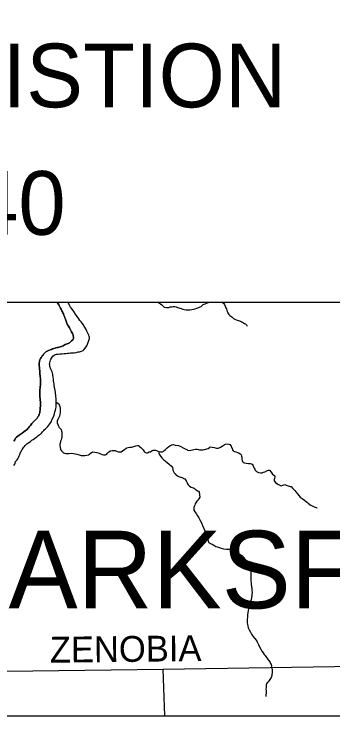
# Model space of a CAD drawing. Extents: x 0 to 34, y 0 to 22.
# Drawn here: x 5.074 to 5.775, y 14.1 to 15.642 of the extents above; entities that cross this region are included whole.
import ezdxf

# ---------------------------------------------------------------- set-up
doc = ezdxf.new("R2010")
doc.units = 0
for name, color, linetype in [('GM_X_Corporation', 7, 'Continuous'), ('GM_X_County_Road', 7, 'Continuous'), ('GM_X_County_Road_Text', 7, 'Continuous'), ('GM_X_Major_River', 7, 'Continuous'), ('GM_X_Minor_River', 7, 'Continuous'), ('GM_X_Township_Road', 7, 'Continuous'), ('GM_X_Township_Text', 7, 'Continuous'), ('SH_Text', 7, 'Continuous')]:
    doc.layers.add(name, color=color, linetype=linetype)

msp = doc.modelspace()

# ---------------------------------------------------------------- linework, layer by layer
at = {"layer": 'GM_X_Corporation'}
msp.add_lwpolyline([(2.1, 20.2456), (2.1, 14.1), (8.0383, 14.1), (8.035, 14.2498), (8.0349, 14.2572), (8.0297, 14.4963), (8.0262, 14.6555), (8.0153, 15.2273), (7.992, 16.4534)], dxfattribs=at)
msp.add_lwpolyline([(3.6901, 15.2048), (3.5209, 15.2041), (2.7366, 15.2014), (2.7422, 14.8151), (2.7753, 14.1537), (2.7761, 14.1), (8.0383, 14.1), (8.035, 14.2498), (8.0349, 14.2572), (8.0297, 14.4963), (8.0262, 14.6555), (8.0153, 15.2273), (6.9496, 15.2134), (6.7394, 15.212), (6.1026, 15.2145), (5.9099, 15.2138), (5.9099, 15.0085), (3.6901, 15.0085)], close=True, dxfattribs=at)
at = {"layer": 'GM_X_County_Road'}
msp.add_lwpolyline([(4.3719, 14.1278), (4.3787, 14.1315), (4.3915, 14.1348), (4.4565, 14.1401), (4.5144, 14.1437), (4.5421, 14.1432), (4.5592, 14.1407), (4.571, 14.1369), (4.5894, 14.1297), (4.6067, 14.1224), (4.6223, 14.1196), (4.6839, 14.1382), (4.8054, 14.1766), (4.8436, 14.1889), (4.8607, 14.1933), (4.8848, 14.1961), (5.4016, 14.2029), (5.8255, 14.2097), (6.2339, 14.2154), (6.3212, 14.2172), (6.4144, 14.2189), (6.6754, 14.2251), (6.9836, 14.2295)], dxfattribs=at)
at = {"layer": 'GM_X_Major_River'}
for points in [[(5.1692, 15.0085), (5.1698, 15.0073), (5.1721, 15.0035), (5.1743, 14.9989), (5.1758, 14.9962), (5.1773, 14.9939), (5.178, 14.992), (5.1791, 14.9901), (5.1802, 14.9878), (5.1814, 14.9859), (5.1825, 14.9832), (5.1836, 14.9805), (5.1847, 14.9778), (5.1858, 14.9748), (5.1873, 14.9717), (5.1887, 14.9671), (5.1898, 14.9633), (5.1917, 14.9595), (5.1935, 14.9561), (5.1958, 14.9526), (5.1976, 14.9496), (5.1991, 14.9469), (5.2006, 14.9442), (5.2025, 14.9404), (5.2036, 14.9373), (5.2039, 14.9354), (5.2047, 14.9324), (5.205, 14.9289), (5.2031, 14.9263), (5.2004, 14.9244)], [(5.2004, 14.9244), (5.2031, 14.9263), (5.205, 14.9289), (5.2047, 14.9324), (5.2039, 14.9354), (5.2036, 14.9373), (5.2025, 14.9404), (5.2006, 14.9442), (5.1991, 14.9469), (5.1976, 14.9496), (5.1958, 14.9526), (5.1935, 14.9561), (5.1917, 14.9595), (5.1898, 14.9633), (5.1887, 14.9671), (5.1873, 14.9717), (5.1858, 14.9748), (5.1847, 14.9778), (5.1836, 14.9805), (5.1825, 14.9832), (5.1814, 14.9859), (5.1802, 14.9878), (5.1791, 14.9901), (5.178, 14.992), (5.1773, 14.9939), (5.1758, 14.9962), (5.1743, 14.9989), (5.1721, 15.0035), (5.1698, 15.0073), (5.1692, 15.0085)], [(5.2322, 14.9111), (5.2345, 14.9149), (5.236, 14.9191), (5.238, 14.9229), (5.2392, 14.927), (5.24, 14.9293), (5.2396, 14.9312), (5.2393, 14.9339), (5.2385, 14.9369), (5.2341, 14.9457), (5.2322, 14.9491), (5.23, 14.9526), (5.2281, 14.9557), (5.2263, 14.9595), (5.2236, 14.9626), (5.2214, 14.9656), (5.2188, 14.9687), (5.2162, 14.9725), (5.2128, 14.9775), (5.2091, 14.9829), (5.2053, 14.9886), (5.2016, 14.9936), (5.1982, 14.9982), (5.1956, 15.0028), (5.193, 15.0074), (5.1925, 15.0085)], [(5.2322, 14.9111), (5.2345, 14.9149), (5.236, 14.9191), (5.238, 14.9229), (5.2392, 14.927), (5.24, 14.9293), (5.2396, 14.9312), (5.2393, 14.9339), (5.2385, 14.9369), (5.2341, 14.9457), (5.2322, 14.9491), (5.23, 14.9526), (5.2281, 14.9557), (5.2263, 14.9595), (5.2236, 14.9626), (5.2214, 14.9656), (5.2188, 14.9687), (5.2162, 14.9725), (5.2128, 14.9775), (5.2091, 14.9829), (5.2053, 14.9886), (5.2016, 14.9936), (5.1982, 14.9982), (5.1956, 15.0028), (5.193, 15.0074), (5.1925, 15.0085)], [(5.2004, 14.9244), (5.1981, 14.9218), (5.1961, 14.9199), (5.1927, 14.9181), (5.1904, 14.9173), (5.1866, 14.9159), (5.1839, 14.9144), (5.1816, 14.9133), (5.1786, 14.9118), (5.1755, 14.9107), (5.1732, 14.9103), (5.1713, 14.9096), (5.1686, 14.9092), (5.166, 14.9085), (5.1641, 14.9078), (5.1614, 14.907), (5.1587, 14.9063), (5.1561, 14.9052), (5.153, 14.9041), (5.1499, 14.9026), (5.1469, 14.9011), (5.1442, 14.8996), (5.1415, 14.8974), (5.1388, 14.8948), (5.1377, 14.8929), (5.1361, 14.891), (5.135, 14.8891), (5.1334, 14.8872), (5.1322, 14.8853), (5.1307, 14.8823), (5.1299, 14.8797), (5.1299, 14.8774), (5.1295, 14.8755), (5.1294, 14.8736), (5.1294, 14.8713), (5.1294, 14.869), (5.1297, 14.866), (5.1297, 14.8637), (5.1301, 14.861), (5.1304, 14.8587), (5.1304, 14.8565), (5.1307, 14.8538), (5.1307, 14.8504), (5.1314, 14.8477), (5.1321, 14.839), (5.132, 14.8355), (5.132, 14.8325), (5.132, 14.8295), (5.1319, 14.8268), (5.1315, 14.8234), (5.1311, 14.8204), (5.131, 14.8173), (5.1306, 14.8131), (5.1306, 14.8093), (5.1309, 14.8052), (5.1309, 14.8014), (5.1312, 14.7975), (5.1315, 14.7937), (5.1319, 14.7903), (5.1322, 14.7873), (5.1322, 14.7839), (5.1321, 14.7804), (5.1317, 14.7766), (5.1313, 14.7721), (5.1308, 14.7687), (5.1304, 14.766), (5.1293, 14.763), (5.1281, 14.7596), (5.1265, 14.7569), (5.1246, 14.7543), (5.1223, 14.7517), (5.1196, 14.749), (5.1173, 14.7468), (5.115, 14.7445), (5.1127, 14.7423), (5.1099, 14.7381), (5.1069, 14.7351), (5.1057, 14.7332), (5.1042, 14.7314), (5.1026, 14.7295), (5.1007, 14.728), (5.0984, 14.7261), (5.0953, 14.7242), (5.0915, 14.7216), (5.0877, 14.7186), (5.085, 14.7168), (5.0823, 14.7149), (5.0796, 14.7126), (5.0773, 14.71), (5.0754, 14.7066), (5.0734, 14.7036)], [(5.0734, 14.7036), (5.0754, 14.7066), (5.0773, 14.71), (5.0796, 14.7126), (5.0823, 14.7149), (5.085, 14.7168), (5.0877, 14.7186), (5.0915, 14.7216), (5.0953, 14.7242), (5.0984, 14.7261), (5.1007, 14.728), (5.1026, 14.7295), (5.1042, 14.7314), (5.1057, 14.7332), (5.1069, 14.7351), (5.1099, 14.7381), (5.1127, 14.7423), (5.115, 14.7445), (5.1173, 14.7468), (5.1196, 14.749), (5.1223, 14.7517), (5.1246, 14.7543), (5.1265, 14.7569), (5.1281, 14.7596), (5.1293, 14.763), (5.1304, 14.766), (5.1308, 14.7687), (5.1313, 14.7721), (5.1317, 14.7766), (5.1321, 14.7804), (5.1322, 14.7839), (5.1322, 14.7873), (5.1319, 14.7903), (5.1315, 14.7937), (5.1312, 14.7975), (5.1309, 14.8014), (5.1309, 14.8052), (5.1306, 14.8093), (5.1306, 14.8131), (5.131, 14.8173), (5.1311, 14.8204), (5.1315, 14.8234), (5.1319, 14.8268), (5.132, 14.8295), (5.132, 14.8325), (5.132, 14.8355), (5.1321, 14.839), (5.1314, 14.8477), (5.1307, 14.8504), (5.1307, 14.8538), (5.1304, 14.8565), (5.1304, 14.8587), (5.1301, 14.861), (5.1297, 14.8637), (5.1297, 14.866), (5.1294, 14.869), (5.1294, 14.8713), (5.1294, 14.8736), (5.1295, 14.8755), (5.1299, 14.8774), (5.1299, 14.8797), (5.1307, 14.8823), (5.1322, 14.8853), (5.1334, 14.8872), (5.135, 14.8891), (5.1361, 14.891), (5.1377, 14.8929), (5.1388, 14.8948), (5.1415, 14.8974), (5.1442, 14.8996), (5.1469, 14.9011), (5.1499, 14.9026), (5.153, 14.9041), (5.1561, 14.9052), (5.1587, 14.9063), (5.1614, 14.907), (5.1641, 14.9078), (5.166, 14.9085), (5.1686, 14.9092), (5.1713, 14.9096), (5.1732, 14.9103), (5.1755, 14.9107), (5.1786, 14.9118), (5.1816, 14.9133), (5.1839, 14.9144), (5.1866, 14.9159), (5.1904, 14.9173), (5.1927, 14.9181), (5.1961, 14.9199), (5.1981, 14.9218), (5.2004, 14.9244)], [(5.0766, 14.6557), (5.0774, 14.6591), (5.0805, 14.6628), (5.0825, 14.6651), (5.084, 14.6681), (5.0852, 14.6711), (5.0864, 14.6742), (5.0875, 14.6772), (5.0887, 14.6795), (5.0903, 14.6821), (5.0914, 14.6844), (5.0926, 14.6863), (5.0949, 14.6897), (5.0965, 14.6915), (5.0984, 14.6942), (5.1019, 14.6979), (5.1065, 14.7005), (5.1099, 14.7032), (5.1134, 14.7062), (5.116, 14.7076), (5.1218, 14.7114), (5.1237, 14.7133), (5.1264, 14.7155), (5.1291, 14.7174), (5.1318, 14.7192), (5.1345, 14.7215), (5.1368, 14.7245), (5.1391, 14.7268), (5.141, 14.729), (5.1429, 14.7305), (5.146, 14.7335), (5.1483, 14.7362), (5.1506, 14.7388), (5.1529, 14.7418), (5.1557, 14.7459), (5.158, 14.752), (5.1607, 14.7573), (5.1619, 14.7611), (5.1631, 14.7645), (5.1639, 14.7679), (5.1651, 14.7721), (5.1659, 14.7755), (5.1663, 14.7781), (5.1663, 14.7815), (5.1664, 14.785), (5.1664, 14.7888), (5.1665, 14.7926), (5.1662, 14.7975), (5.1658, 14.8017), (5.1655, 14.8051), (5.1652, 14.8085), (5.1648, 14.8116), (5.1645, 14.815), (5.1638, 14.8188), (5.1627, 14.8226), (5.1623, 14.8261), (5.162, 14.8295), (5.1616, 14.8325), (5.1609, 14.836), (5.1606, 14.8382), (5.1606, 14.8409), (5.1602, 14.8432), (5.1599, 14.8451), (5.1595, 14.8478), (5.1592, 14.8504), (5.1585, 14.8531), (5.1574, 14.8562), (5.1563, 14.8592), (5.1548, 14.8619), (5.1529, 14.868), (5.1526, 14.8707), (5.1522, 14.8729), (5.1523, 14.876), (5.1531, 14.879), (5.1539, 14.8817), (5.155, 14.8839), (5.1566, 14.8862), (5.1581, 14.8884), (5.1593, 14.8903), (5.162, 14.8926), (5.165, 14.8944), (5.167, 14.8948), (5.1708, 14.8951), (5.1749, 14.8955), (5.1795, 14.8958), (5.1845, 14.8961), (5.1879, 14.8965), (5.1917, 14.8968), (5.1943, 14.8971), (5.1978, 14.8975), (5.202, 14.8978), (5.2061, 14.8981), (5.2107, 14.8988), (5.2149, 14.8996), (5.2179, 14.8999), (5.2202, 14.9006), (5.2225, 14.9014), (5.2256, 14.9032), (5.2275, 14.9047), (5.2294, 14.9074), (5.2322, 14.9111)], [(5.0766, 14.6557), (5.0774, 14.6591), (5.0805, 14.6628), (5.0825, 14.6651), (5.084, 14.6681), (5.0852, 14.6711), (5.0864, 14.6742), (5.0875, 14.6772), (5.0887, 14.6795), (5.0903, 14.6821), (5.0914, 14.6844), (5.0926, 14.6863), (5.0949, 14.6897), (5.0965, 14.6915), (5.0984, 14.6942), (5.1019, 14.6979), (5.1065, 14.7005), (5.1099, 14.7032), (5.1134, 14.7062), (5.116, 14.7076), (5.1218, 14.7114), (5.1237, 14.7133), (5.1264, 14.7155), (5.1291, 14.7174), (5.1318, 14.7192), (5.1345, 14.7215), (5.1368, 14.7245), (5.1391, 14.7268), (5.141, 14.729), (5.1429, 14.7305), (5.146, 14.7335), (5.1483, 14.7362), (5.1506, 14.7388), (5.1529, 14.7418), (5.1557, 14.7459), (5.158, 14.752), (5.1607, 14.7573), (5.1619, 14.7611), (5.1631, 14.7645), (5.1639, 14.7679), (5.1651, 14.7721), (5.1659, 14.7755), (5.1663, 14.7781), (5.1663, 14.7815), (5.1664, 14.785), (5.1664, 14.7888), (5.1665, 14.7926), (5.1662, 14.7975), (5.1658, 14.8017), (5.1655, 14.8051), (5.1652, 14.8085), (5.1648, 14.8116), (5.1645, 14.815), (5.1638, 14.8188), (5.1627, 14.8226), (5.1623, 14.8261), (5.162, 14.8295), (5.1616, 14.8325), (5.1609, 14.836), (5.1606, 14.8382), (5.1606, 14.8409), (5.1602, 14.8432), (5.1599, 14.8451), (5.1595, 14.8478), (5.1592, 14.8504), (5.1585, 14.8531), (5.1574, 14.8562), (5.1563, 14.8592), (5.1548, 14.8619), (5.1529, 14.868), (5.1526, 14.8707), (5.1522, 14.8729), (5.1523, 14.876), (5.1531, 14.879), (5.1539, 14.8817), (5.155, 14.8839), (5.1566, 14.8862), (5.1581, 14.8884), (5.1593, 14.8903), (5.162, 14.8926), (5.165, 14.8944), (5.167, 14.8948), (5.1708, 14.8951), (5.1749, 14.8955), (5.1795, 14.8958), (5.1845, 14.8961), (5.1879, 14.8965), (5.1917, 14.8968), (5.1943, 14.8971), (5.1978, 14.8975), (5.202, 14.8978), (5.2061, 14.8981), (5.2107, 14.8988), (5.2149, 14.8996), (5.2179, 14.8999), (5.2202, 14.9006), (5.2225, 14.9014), (5.2256, 14.9032), (5.2275, 14.9047), (5.2294, 14.9074), (5.2322, 14.9111)], [(5.0735, 14.65), (5.0755, 14.653), (5.0766, 14.6557)], [(5.0735, 14.65), (5.0755, 14.653), (5.0766, 14.6557)]]:
    msp.add_lwpolyline(points, dxfattribs=at)
at = {"layer": 'GM_X_Minor_River'}
for points in [[(5.3908, 15.0085), (5.3915, 15.0081), (5.3956, 15.0054), (5.399, 15.003), (5.402, 15), (5.4043, 14.9984), (5.4088, 14.9972), (5.4118, 14.9972), (5.4141, 14.9975), (5.4172, 14.9986), (5.4206, 14.999), (5.4237, 14.9993), (5.4271, 14.9993), (5.4305, 14.9985), (5.4335, 14.9977), (5.4362, 14.9969), (5.4388, 14.9957), (5.4411, 14.9949), (5.443, 14.9942), (5.4449, 14.9934), (5.4479, 14.993), (5.4521, 14.9925), (5.4559, 14.9921), (5.4601, 14.9924), (5.4646, 14.9931), (5.4688, 14.9938), (5.4723, 14.9946), (5.4761, 14.9957), (5.4799, 14.9975), (5.4833, 14.9986), (5.4852, 14.9994), (5.4899, 15.0039), (5.4941, 15.0053), (5.5017, 15.0085)], [(5.5325, 15.0085), (5.5332, 15.0079), (5.5351, 15.006), (5.5366, 15.0037), (5.5381, 15.0002), (5.5396, 14.9964), (5.5411, 14.9941), (5.5418, 14.9918), (5.5425, 14.9884)], [(5.5425, 14.9884), (5.544, 14.9854), (5.5459, 14.9823), (5.5485, 14.9796), (5.5526, 14.9765), (5.5568, 14.9734), (5.5605, 14.9711), (5.5643, 14.9695), (5.567, 14.9687), (5.57, 14.9679), (5.5719, 14.9672), (5.5742, 14.966), (5.5764, 14.9648), (5.5787, 14.9637), (5.5806, 14.9625), (5.5825, 14.9617), (5.5851, 14.959), (5.5864, 14.9566)], [(5.1664, 14.7892), (5.1721, 14.7857), (5.1732, 14.7834), (5.1743, 14.7799), (5.175, 14.7765), (5.1757, 14.7685), (5.1757, 14.7662), (5.1749, 14.7628), (5.1737, 14.7587), (5.1717, 14.7545), (5.1702, 14.7511), (5.169, 14.7488), (5.1686, 14.7466), (5.1689, 14.7439), (5.17, 14.7405), (5.1719, 14.737), (5.1734, 14.734), (5.1749, 14.732), (5.1775, 14.729), (5.1786, 14.7259), (5.1793, 14.7232), (5.1793, 14.7191), (5.1792, 14.716), (5.1788, 14.7134), (5.1784, 14.7099), (5.1772, 14.7065), (5.1764, 14.7039), (5.176, 14.7016), (5.1756, 14.6993), (5.1748, 14.6971), (5.1748, 14.6944), (5.1751, 14.6906), (5.1762, 14.6856), (5.1781, 14.6822), (5.1807, 14.6799), (5.183, 14.6783), (5.1852, 14.6776), (5.1875, 14.6768), (5.1906, 14.6764), (5.1947, 14.6767), (5.2001, 14.6774), (5.2046, 14.6769), (5.2084, 14.6761), (5.2118, 14.6753), (5.2171, 14.6734), (5.2213, 14.6722), (5.2255, 14.6721), (5.2297, 14.6721), (5.2342, 14.6728), (5.2377, 14.6735), (5.2396, 14.675), (5.2415, 14.6765), (5.2465, 14.6799), (5.2514, 14.6798), (5.256, 14.6786), (5.2609, 14.677), (5.2643, 14.6762), (5.2677, 14.6743), (5.2703, 14.6735), (5.2726, 14.6735), (5.2753, 14.6738), (5.2776, 14.6749), (5.2795, 14.6772), (5.2826, 14.6802), (5.286, 14.6821), (5.2898, 14.6832), (5.2933, 14.6835), (5.2963, 14.6831), (5.2993, 14.6815), (5.3027, 14.6803), (5.305, 14.6799), (5.3069, 14.6799), (5.3096, 14.6806), (5.3123, 14.6821), (5.315, 14.6844), (5.3169, 14.6855), (5.3203, 14.6881), (5.3222, 14.6889), (5.3245, 14.69), (5.3291, 14.6903), (5.3325, 14.6906), (5.3348, 14.691), (5.3375, 14.6921), (5.3417, 14.6936), (5.3455, 14.6943), (5.3474, 14.6943), (5.35, 14.6923), (5.353, 14.69), (5.3557, 14.6869), (5.3579, 14.6843), (5.3601, 14.6812), (5.3613, 14.6793), (5.3632, 14.6785), (5.3654, 14.6777), (5.3677, 14.6784)], [(5.3677, 14.6784), (5.3712, 14.6799), (5.3742, 14.6806), (5.3777, 14.6829), (5.3799, 14.6836), (5.3822, 14.684), (5.3849, 14.6836), (5.3872, 14.6831), (5.3898, 14.682), (5.3928, 14.6812), (5.3959, 14.6804), (5.3982, 14.6804), (5.4001, 14.6803), (5.402, 14.6811), (5.4043, 14.6833), (5.407, 14.6852), (5.4089, 14.6878), (5.4108, 14.6893), (5.4143, 14.6919), (5.4162, 14.6931), (5.4181, 14.6942), (5.42, 14.6953), (5.4219, 14.6957), (5.4246, 14.696), (5.4284, 14.6952), (5.4356, 14.694), (5.4409, 14.692), (5.4458, 14.6893), (5.4499, 14.687), (5.4537, 14.6854), (5.4556, 14.6842), (5.4586, 14.6834), (5.4624, 14.6838), (5.4662, 14.6849), (5.4693, 14.6856), (5.4727, 14.6863), (5.4746, 14.6863), (5.4765, 14.6859), (5.4792, 14.6851), (5.4815, 14.6847), (5.4845, 14.6847), (5.4887, 14.6846), (5.4929, 14.6853), (5.5009, 14.6875), (5.5036, 14.6901), (5.5055, 14.6912), (5.5093, 14.6908), (5.5142, 14.6896), (5.5191, 14.6884), (5.5226, 14.6884), (5.5252, 14.6887), (5.5275, 14.6906), (5.5313, 14.6925), (5.534, 14.6939), (5.5382, 14.6973), (5.5424, 14.6976), (5.5462, 14.6968), (5.5485, 14.6961), (5.5511, 14.6926), (5.5522, 14.6899), (5.5533, 14.6873), (5.5544, 14.6846), (5.5556, 14.6827), (5.559, 14.6807), (5.5616, 14.6799), (5.565, 14.6791), (5.5684, 14.678), (5.5711, 14.6756), (5.5733, 14.6737), (5.5744, 14.6707), (5.5748, 14.6688), (5.5747, 14.6665), (5.5751, 14.6638), (5.5758, 14.6615), (5.5766, 14.6592), (5.5781, 14.6569), (5.5807, 14.6558), (5.5841, 14.655), (5.5891, 14.6549), (5.591, 14.6549), (5.5929, 14.6549), (5.5974, 14.6533), (5.5996, 14.6495), (5.6007, 14.6472), (5.6022, 14.6445), (5.6033, 14.6422), (5.6041, 14.6403), (5.6067, 14.6372), (5.6097, 14.6357), (5.6116, 14.6349), (5.6158, 14.6344), (5.6196, 14.6344), (5.6227, 14.6355), (5.6253, 14.6366), (5.6272, 14.637), (5.6291, 14.6385), (5.6314, 14.6396), (5.6333, 14.6403), (5.6353, 14.6403), (5.639, 14.6353), (5.6424, 14.6311)], [(5.393, 14.6811), (5.3924, 14.6774), (5.3928, 14.6751), (5.3958, 14.6709), (5.3991, 14.6674), (5.4014, 14.6651), (5.4036, 14.6628), (5.4067, 14.6601), (5.4104, 14.6566), (5.4153, 14.6528), (5.4202, 14.6485), (5.4224, 14.6459), (5.4228, 14.6424), (5.4231, 14.6398), (5.4242, 14.6371), (5.4257, 14.6344), (5.428, 14.6317), (5.4306, 14.629), (5.4329, 14.6279), (5.4351, 14.6267), (5.4378, 14.6252), (5.4404, 14.6244), (5.445, 14.6228), (5.4476, 14.622), (5.4495, 14.6208), (5.451, 14.6185), (5.4532, 14.6151), (5.4543, 14.612), (5.4555, 14.6097), (5.457, 14.6074), (5.46, 14.6047), (5.4634, 14.6024), (5.4679, 14.6009), (5.4702, 14.6001), (5.4724, 14.5985), (5.4743, 14.5966), (5.4773, 14.5947), (5.4796, 14.5935), (5.4811, 14.5916), (5.4821, 14.5805), (5.4805, 14.5771), (5.4778, 14.5741), (5.4755, 14.5719), (5.4736, 14.5685), (5.4724, 14.5658), (5.4712, 14.5632), (5.4701, 14.5605), (5.4693, 14.5583), (5.4693, 14.5552), (5.4696, 14.5522), (5.4711, 14.5487), (5.4741, 14.5445), (5.4774, 14.5399), (5.4804, 14.535), (5.4834, 14.5296), (5.4864, 14.5239), (5.4886, 14.5185), (5.4912, 14.512), (5.4934, 14.5067), (5.4956, 14.5009), (5.4974, 14.4952), (5.4992, 14.4895), (5.5007, 14.4849), (5.5018, 14.4819), (5.5037, 14.4803), (5.506, 14.4788), (5.5094, 14.4772), (5.5135, 14.4749), (5.5177, 14.4722), (5.5237, 14.4706), (5.5294, 14.4686), (5.5347, 14.4674), (5.5408, 14.4666), (5.5461, 14.4661), (5.5507, 14.4653), (5.5552, 14.4645), (5.5597, 14.4626), (5.5635, 14.4606), (5.5669, 14.4579), (5.5707, 14.4552), (5.5752, 14.4514), (5.5782, 14.4483), (5.5812, 14.4444), (5.5842, 14.441), (5.5864, 14.4379), (5.5912, 14.4265), (5.5927, 14.4223), (5.5942, 14.4177), (5.5945, 14.4131), (5.5944, 14.4078), (5.5944, 14.404), (5.5947, 14.3998), (5.5947, 14.396), (5.595, 14.393), (5.595, 14.3903), (5.5953, 14.388), (5.5957, 14.3857), (5.5961, 14.3838), (5.5964, 14.3812), (5.5967, 14.3785), (5.5971, 14.3755)], [(5.6424, 14.6311), (5.645, 14.6292), (5.6473, 14.6276), (5.6472, 14.6257), (5.6464, 14.6219), (5.6456, 14.6196), (5.6456, 14.6166), (5.6486, 14.6131), (5.6539, 14.6093), (5.6595, 14.6062), (5.6614, 14.6054), (5.6649, 14.6069), (5.6672, 14.608), (5.6691, 14.6083), (5.6725, 14.6068), (5.6766, 14.6052), (5.6808, 14.6044), (5.6831, 14.604), (5.6868, 14.5998), (5.6891, 14.5975), (5.691, 14.5952), (5.6932, 14.5921), (5.697, 14.5879), (5.7, 14.5844), (5.7033, 14.581), (5.7075, 14.5775), (5.7124, 14.574), (5.7165, 14.5709), (5.7192, 14.5686), (5.721, 14.5671), (5.7244, 14.5644), (5.7267, 14.5628), (5.7297, 14.5613), (5.7335, 14.5597), (5.7361, 14.5589), (5.738, 14.5577), (5.7399, 14.5573), (5.7407, 14.5569)], [(5.5971, 14.3755), (5.5974, 14.3713), (5.597, 14.3679), (5.597, 14.3641), (5.5961, 14.3599), (5.5953, 14.3553), (5.5937, 14.3497), (5.5922, 14.3444), (5.5906, 14.3394), (5.5894, 14.3353), (5.5886, 14.3311), (5.5878, 14.3273), (5.5873, 14.322), (5.5869, 14.3171), (5.5865, 14.3129), (5.5864, 14.3095), (5.5867, 14.3053), (5.5871, 14.3011), (5.5878, 14.2977), (5.5889, 14.2939), (5.5911, 14.2893), (5.5937, 14.2843), (5.5963, 14.2793), (5.5993, 14.2751), (5.603, 14.2701), (5.606, 14.2663), (5.6087, 14.2625), (5.6112, 14.2571), (5.6138, 14.2517), (5.6164, 14.2464), (5.6191, 14.2422), (5.6217, 14.2384), (5.6239, 14.2353), (5.6262, 14.233), (5.6277, 14.2307), (5.6329, 14.2234), (5.634, 14.2215), (5.6355, 14.2196), (5.637, 14.2177), (5.6381, 14.2154), (5.6392, 14.2127), (5.6399, 14.2096), (5.6403, 14.207), (5.6407, 14.2051), (5.6414, 14.2016), (5.6413, 14.1997), (5.6413, 14.1971), (5.6413, 14.1944), (5.6409, 14.1914), (5.6405, 14.1887), (5.6397, 14.1865), (5.6389, 14.1842), (5.6381, 14.1823), (5.6366, 14.1804), (5.635, 14.1782), (5.6327, 14.1751), (5.6304, 14.1729), (5.6288, 14.1706), (5.6281, 14.1687), (5.628, 14.1668), (5.628, 14.1646), (5.628, 14.1615), (5.6279, 14.1585), (5.6283, 14.1554), (5.6282, 14.1532), (5.6282, 14.1509), (5.6278, 14.1456), (5.6274, 14.1437), (5.6274, 14.1429)]]:
    msp.add_lwpolyline(points, dxfattribs=at)
at = {"layer": 'GM_X_Township_Road'}
msp.add_line((5.4052, 14.1), (5.4016, 14.2029), dxfattribs=at)
at = {"layer": 'SH_Text'}
msp.add_lwpolyline([(3.6901, 15.7256), (5.9099, 15.7256), (5.9099, 15.0085), (3.6901, 15.0085)], close=True, dxfattribs=at)

# ---------------------------------------------------------------- texts
at = {"layer": 'GM_X_County_Road_Text'}
msp.add_text('ZENOBIA', height=0.05682, rotation=0.6212, dxfattribs=at).set_placement((5.1528, 14.2169))
at = {"layer": 'GM_X_Township_Text'}
msp.add_text('CLARKSFIELD', height=0.170455, rotation=0, dxfattribs=at).set_placement((4.7704, 14.3364))
at = {"layer": 'SH_Text'}
for s, p in [('BEGIN ACQUISTION', (3.8732, 15.4371)), ('SLM 2.40', (4.3862, 15.1571))]:
    msp.add_text(s, height=0.14, dxfattribs=at).set_placement(p)

doc.saveas('drawing.dxf')
